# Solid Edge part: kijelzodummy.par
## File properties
Author: morva
Template: iso metric part.par
Last saved by: morva
Revision: 2
Application: Solid Edge
Accuracy: 0.990
Username: morva
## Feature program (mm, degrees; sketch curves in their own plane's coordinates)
sketch for "unnamed Protrusion 1" plane through (0, 0, 0) normal (0, 0, 1) x-axis (1, 0, 0)
  line (-40.5, 24) -> (40.5, 24)
  line (40.5, 24) -> (40.5, -24)
  line (40.5, -24) -> (-40.5, -24)
  line (-40.5, -24) -> (-40.5, 24)
  dimension (linear) = 40.5
  dimension (linear) = 40.5
extrude "unnamed Protrusion 1" add finite 8 along +normal
sketch for "ExtrudedProtrusion_2" #1 plane through (0, 0, 0) normal (1, 0, 0) x-axis (0, 1, 0)
  circle centre (0, -12) radius 12.5
sketch for "ExtrudedProtrusion_2" #2 plane through (0, 0, 0) normal (1, 0, 0) x-axis (0, 1, 0)
  circle centre (0, -12) radius 11
extrude "ExtrudedProtrusion_2" add finite 10 symmetric
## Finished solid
Body 1: solid body, 10 faces, 20 edges, 12 vertices.
  Faces by surface: plane 8, cylinder 2
  Edges by curve: line 16, circle 4
Bounding box of the edges (mm): 81.000 x 48.000 x 32.500, from (-40.5, -24, -24.5) to (40.5, 24, 8).
Cylindrical faces by radius (mm): R11 x1, R12.5 x1
Planar faces by outward normal: +x 2, +y 1, +z 1, -x 2, -y 1, -z 1
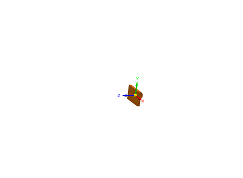
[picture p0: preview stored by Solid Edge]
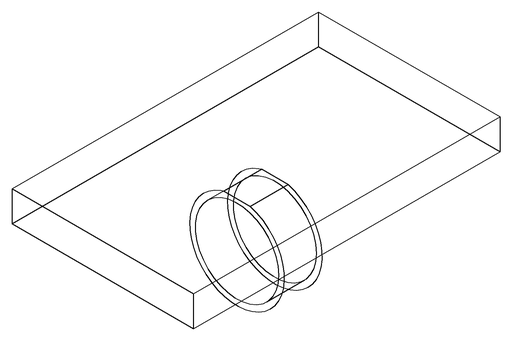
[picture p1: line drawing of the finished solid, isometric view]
